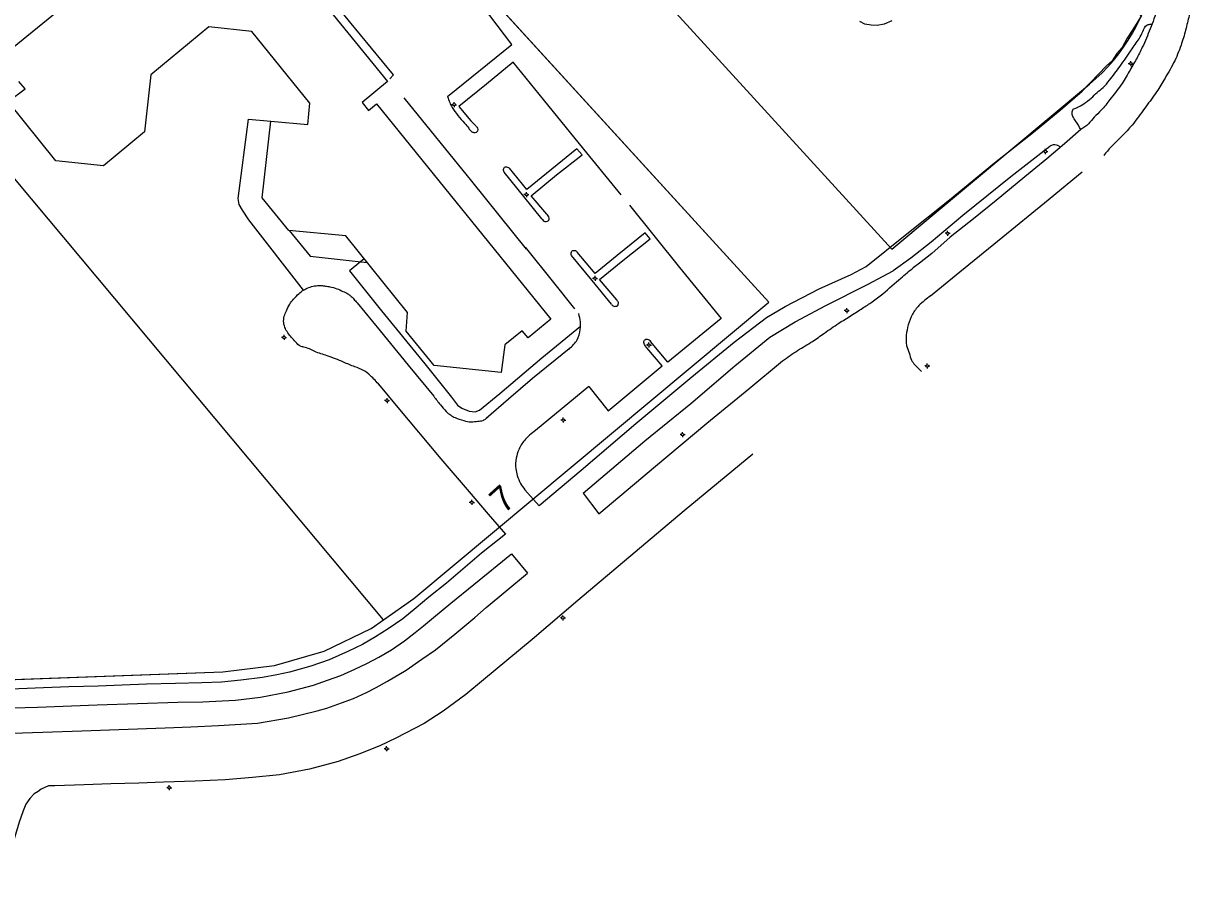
# Model space of a CAD drawing. Extents: x 1517229 to 1518128, y 6494851 to 6495271.
# Drawn here: x 1517875.8 to 1518062.3, y 6494915.9 to 6495054.4 of the extents above; entities that cross this region are included whole.
import ezdxf

# ---------------------------------------------------------------- set-up
doc = ezdxf.new("R2010")
doc.units = 0
doc.layers.add('Karta', color=7, linetype='Continuous')

msp = doc.modelspace()

# ---------------------------------------------------------------- linework, layer by layer
at = {"layer": 'Karta'}
for p, q in [((1517860.04, 6495186.49), (1518013.12, 6495018.67)), ((1517881.78, 6495132.98), (1517993.7, 6495010.28)), ((1517932.72, 6494960.01), (1517858.73, 6495048.55)), ((1518050.74, 6495048.03), (1518050.54, 6495048.03)), ((1518050.94, 6495048.23), (1518050.94, 6495048.43)), ((1518050.94, 6495047.83), (1518050.94, 6495047.63)), ((1518051.14, 6495048.03), (1518051.34, 6495048.03)), ((1518013.12, 6495018.67), (1518044.42, 6495044.79)), ((1517943.7, 6495041.55), (1517943.5, 6495041.55)), ((1517943.9, 6495041.75), (1517943.9, 6495041.95)), ((1517943.9, 6495041.35), (1517943.9, 6495041.15)), ((1517944.1, 6495041.55), (1517944.3, 6495041.55)), ((1518037.21, 6495034.14), (1518037.01, 6495034.14)), ((1518037.41, 6495034.34), (1518037.41, 6495034.54)), ((1518037.41, 6495033.94), (1518037.41, 6495033.74)), ((1518037.61, 6495034.14), (1518037.81, 6495034.14)), ((1517955.14, 6495027.31), (1517954.94, 6495027.31)), ((1517955.34, 6495027.51), (1517955.34, 6495027.71)), ((1517955.34, 6495027.11), (1517955.34, 6495026.91)), ((1517955.54, 6495027.31), (1517955.74, 6495027.31)), ((1518021.76, 6495021.2), (1518021.56, 6495021.2)), ((1518021.96, 6495021.4), (1518021.96, 6495021.6)), ((1518021.96, 6495021), (1518021.96, 6495020.8)), ((1518022.16, 6495021.2), (1518022.36, 6495021.2)), ((1517929.69, 6495017.16), (1517927.33, 6495015.24)), ((1517965.99, 6495014.06), (1517965.79, 6495014.06)), ((1517966.19, 6495014.26), (1517966.19, 6495014.46)), ((1517966.19, 6495013.86), (1517966.19, 6495013.66)), ((1517966.39, 6495014.06), (1517966.59, 6495014.06)), ((1517937.5, 6494963.37), (1517993.7, 6495010.28)), ((1517937.5, 6494963.37), (1517993.7, 6495010.28)), ((1518005.81, 6495008.96), (1518005.61, 6495008.96)), ((1518006.01, 6495009.16), (1518006.01, 6495009.36)), ((1518006.01, 6495008.76), (1518006.01, 6495008.56)), ((1518006.21, 6495008.96), (1518006.41, 6495008.96)), ((1517916.79, 6495004.71), (1517916.59, 6495004.71)), ((1517916.99, 6495004.91), (1517916.99, 6495005.11)), ((1517916.99, 6495004.51), (1517916.99, 6495004.31)), ((1517917.19, 6495004.71), (1517917.39, 6495004.71)), ((1517974.71, 6495003.71), (1517974.71, 6495003.91)), ((1517977.69, 6495000.8), (1517974.98, 6495004.06)), ((1517974.51, 6495003.51), (1517974.31, 6495003.51)), ((1517974.71, 6495003.31), (1517974.71, 6495003.11)), ((1517974.91, 6495003.51), (1517975.11, 6495003.51)), ((1518018.54, 6495000.2), (1518018.34, 6495000.2)), ((1518018.74, 6495000.4), (1518018.74, 6495000.6)), ((1518018.94, 6495000.2), (1518019.14, 6495000.2)), ((1518018.74, 6495000), (1518018.74, 6494999.8)), ((1517965.2, 6494996.93), (1517956.78, 6494990)), ((1517933.09, 6494994.71), (1517932.89, 6494994.71)), ((1517933.29, 6494994.91), (1517933.29, 6494995.11)), ((1517933.29, 6494994.51), (1517933.29, 6494994.31)), ((1517933.49, 6494994.71), (1517933.69, 6494994.71)), ((1517960.97, 6494991.63), (1517960.77, 6494991.63)), ((1517961.17, 6494991.83), (1517961.17, 6494992.03)), ((1517961.17, 6494991.43), (1517961.17, 6494991.23)), ((1517961.37, 6494991.63), (1517961.57, 6494991.63)), ((1517979.83, 6494989.34), (1517979.63, 6494989.34)), ((1517980.03, 6494989.54), (1517980.03, 6494989.74)), ((1517980.03, 6494989.14), (1517980.03, 6494988.94)), ((1517980.23, 6494989.34), (1517980.43, 6494989.34)), ((1517941.8, 6494985.5), (1517946.29, 6494980.3)), ((1517955.08, 6494980.59), (1517957.37, 6494978.04)), ((1517946.5, 6494978.61), (1517946.3, 6494978.61)), ((1517946.7, 6494978.81), (1517946.7, 6494979.01)), ((1517946.7, 6494978.41), (1517946.7, 6494978.21)), ((1517946.9, 6494978.61), (1517947.1, 6494978.61)), ((1517932.72, 6494960.01), (1517937.5, 6494963.37)), ((1517930.77, 6494958.64), (1517932.72, 6494960.01)), ((1517960.9, 6494960.33), (1517960.7, 6494960.33)), ((1517961.1, 6494960.53), (1517961.1, 6494960.73)), ((1517961.1, 6494960.13), (1517961.1, 6494959.93)), ((1517961.3, 6494960.33), (1517961.5, 6494960.33)), ((1517923.36, 6494955.07), (1517930.77, 6494958.64)), ((1517915.47, 6494952.77), (1517923.36, 6494955.07)), ((1517784.48, 6494947.28), (1517907.3, 6494951.79)), ((1517907.3, 6494951.79), (1517915.47, 6494952.77)), ((1517933.02, 6494939.61), (1517932.82, 6494939.61)), ((1517933.22, 6494939.81), (1517933.22, 6494940.01)), ((1517933.22, 6494939.41), (1517933.22, 6494939.21)), ((1517933.42, 6494939.61), (1517933.62, 6494939.61)), ((1517898.63, 6494933.44), (1517898.43, 6494933.44)), ((1517898.83, 6494933.64), (1517898.83, 6494933.84)), ((1517898.83, 6494933.24), (1517898.83, 6494933.04)), ((1517899.03, 6494933.44), (1517899.23, 6494933.44))]:
    msp.add_line(p, q, dxfattribs=at)
for points in [[(1517844.68, 6495173.66), (1517881.78, 6495132.98), (1517993.7, 6495010.28)], [(1517933.73, 6495045.66), (1517934.33, 6495046.26), (1517927.37, 6495054.74), (1517921.21, 6495062.29), (1517913.73, 6495071.44), (1517908.14, 6495078.37), (1517907.09, 6495077.52)], [(1517870.88, 6495048), (1517907.09, 6495077.52), (1517933.35, 6495045.23), (1517929.35, 6495041.89), (1517930.34, 6495040.63), (1517931.6, 6495041.66), (1517959.21, 6495007.63), (1517955.6, 6495004.66), (1517954.66, 6495005.75), (1517951.91, 6495003.55), (1517951.34, 6494999.16), (1517940.72, 6495000.25), (1517936.32, 6495005.72), (1517936.54, 6495008.66), (1517926.77, 6495020.79), (1517917.76, 6495021.62), (1517913.56, 6495026.79), (1517914.92, 6495038.96), (1517920.76, 6495038.39), (1517921.1, 6495041.77), (1517911.88, 6495053.14), (1517905.12, 6495053.86), (1517895.91, 6495046.25), (1517894.94, 6495037.25), (1517888.42, 6495031.87), (1517880.89, 6495032.64), (1517873.38, 6495042.06), (1517876.03, 6495044.05), (1517875.06, 6495045.24)], [(1517942.87, 6495042.85), (1517953.03, 6495051.06), (1517944.76, 6495062.04), (1517943.82, 6495061.29)], [(1518047.05, 6495057.36), (1518050.19, 6495056.46), (1518052.3, 6495055.83), (1518052.64, 6495055.68), (1518051.87, 6495054.47), (1518051.15, 6495053.28), (1518050.38, 6495052.07), (1518049.57, 6495050.61), (1518048.73, 6495049.65), (1518047.98, 6495048.5), (1518047.11, 6495047.69)], [(1518013.12, 6495054.84), (1518011.94, 6495054.3), (1518010.79, 6495054.09), (1518009.89, 6495054.12), (1518008.86, 6495054.3), (1518008.08, 6495054.72)], [(1517970.3, 6495027.28), (1517964.43, 6495034.5), (1517958.01, 6495042.35), (1517953.24, 6495048.28), (1517949, 6495044.8), (1517944.66, 6495041.29), (1517946.52, 6495038.97), (1517947.31, 6495038.18)], [(1518009.06, 6495015.92), (1518015.25, 6495020.88), (1518022.28, 6495026.48), (1518029.37, 6495032.34), (1518035.55, 6495037.22), (1518039.78, 6495040.67), (1518043.23, 6495043.67), (1518047.11, 6495047.69)], [(1517955.36, 6495018.69), (1517946.68, 6495029.43), (1517936.02, 6495042.61)], [(1517920.09, 6495012.22), (1517911.41, 6495023.35), (1517910.42, 6495024.84), (1517909.92, 6495025.77), (1517909.74, 6495026.69), (1517911.35, 6495039.25), (1517914.92, 6495038.96)], [(1518043.04, 6495037.61), (1518040.43, 6495035.33), (1518037.64, 6495032.99), (1518034.19, 6495030.13), (1518029.63, 6495026.41), (1518026.06, 6495023.49), (1518022.35, 6495020.56), (1518019.48, 6495018.02), (1518017.53, 6495016.45), (1518016.52, 6495015.74)], [(1517958.56, 6495024.23), (1517956.07, 6495027.14), (1517960.08, 6495030.46), (1517964.15, 6495033.64), (1517963.32, 6495034.56), (1517955.41, 6495028.14), (1517952.66, 6495031.48)], [(1518038.12, 6495034.95), (1518031.98, 6495030.13), (1518024.36, 6495024.01), (1518019.35, 6495019.77), (1518016.16, 6495017.24), (1518013.33, 6495015.28)], [(1517957.79, 6495023.5), (1517954.95, 6495027.04), (1517951.8, 6495030.85)], [(1518019.24, 6495011.3), (1518023.91, 6495015.09), (1518030.68, 6495020.62), (1518037.31, 6495026.03), (1518043.23, 6495030.91)], [(1517971.62, 6495025.65), (1517979.57, 6495015.78), (1517986.13, 6495007.7), (1517977.69, 6495000.8)], [(1517917.79, 6495021.62), (1517921.12, 6495017.59), (1517930.16, 6495016.58)], [(1517969.63, 6495010.64), (1517966.92, 6495013.89), (1517970.59, 6495016.87), (1517974.9, 6495020.32), (1517974.14, 6495021.25), (1517969.7, 6495017.7), (1517966.22, 6495014.85), (1517963.37, 6495018.23)], [(1517955.12, 6495018.99), (1517959.6, 6495013.39), (1517962.95, 6495009.26)], [(1517968.77, 6495009.98), (1517965.76, 6495013.72), (1517962.48, 6495017.7)], [(1517927.33, 6495015.24), (1517932.4, 6495008.93), (1517939.24, 6495000.53), (1517943.47, 6494995.26)], [(1517988.19, 6495003.96), (1517993.31, 6495007.88), (1517996.26, 6495009.62), (1518001.65, 6495012.4), (1518006.7, 6495014.66), (1518009.06, 6495015.92)], [(1517988.32, 6495000.24), (1517993.83, 6495004.75), (1517997.83, 6495007.18), (1518002.7, 6495009.79), (1518009.31, 6495013.1), (1518013.33, 6495015.28)], [(1517928.54, 6495010.21), (1517932.21, 6495005.74), (1517936.65, 6495000.31), (1517940.69, 6494995.4)], [(1517943.47, 6494995.26), (1517944.41, 6494994.02), (1517945.13, 6494993.5), (1517946.3, 6494993.05), (1517947.21, 6494992.92), (1517947.92, 6494993.18), (1517951.11, 6494995.85), (1517957.75, 6495001.51), (1517963.87, 6495006.52)], [(1517957.33, 6494978.09), (1517963.98, 6494983.71), (1517972.63, 6494991.07), (1517981.48, 6494998.49), (1517988.19, 6495003.96)], [(1517962.12, 6495002.89), (1517956.32, 6494998.22), (1517952.51, 6494994.94), (1517948.98, 6494991.88)], [(1517965.2, 6494996.93), (1517968.24, 6494993.12), (1517976.79, 6495000.21), (1517974.4, 6495003.06)], [(1517964.31, 6494980.07), (1517966.78, 6494976.81), (1517975.76, 6494984.36), (1517983.89, 6494991.13), (1517990.53, 6494996.6), (1517995.86, 6495001.03)], [(1517964.31, 6494980.06), (1517974.07, 6494988.33), (1517981.35, 6494994.26), (1517988.32, 6495000.24)], [(1517931.95, 6494997.31), (1517935.01, 6494993.65), (1517941.8, 6494985.5)], [(1517991.15, 6494986.25), (1517980.28, 6494977.28), (1517972.55, 6494970.74), (1517963.46, 6494963.09)], [(1517946.29, 6494980.3), (1517949.27, 6494976.75), (1517952.02, 6494973.57)], [(1517952.02, 6494973.57), (1517948.24, 6494970.56), (1517942.7, 6494965.83), (1517939.9, 6494963.59), (1517937.87, 6494961.94), (1517935.77, 6494960.16), (1517933.49, 6494958.58), (1517931.46, 6494957.32)], [(1517943.37, 6494962.65), (1517947.04, 6494965.59), (1517952.96, 6494970.49), (1517955.53, 6494967.39)], [(1517948.97, 6494961.95), (1517952.09, 6494964.54), (1517955.53, 6494967.39)], [(1517930.77, 6494958.64), (1517932.72, 6494960.01), (1517937.5, 6494963.37)], [(1517963.46, 6494963.09), (1517956.26, 6494956.9), (1517948.56, 6494950.5)], [(1517921.65, 6494949.68), (1517923.89, 6494950.45), (1517925.99, 6494951.22), (1517928.2, 6494952.2), (1517930.09, 6494953.11), (1517931.98, 6494954.1), (1517933.98, 6494955.29), (1517936.05, 6494956.69), (1517937.73, 6494958.02), (1517939.06, 6494959.07), (1517940.63, 6494960.4), (1517943.37, 6494962.65)], [(1517922.25, 6494945.62), (1517923.75, 6494946.04), (1517926.1, 6494946.88), (1517927.96, 6494947.58), (1517930.02, 6494948.52), (1517931.56, 6494949.33), (1517933.35, 6494950.31), (1517936.29, 6494952.06), (1517938.81, 6494953.78), (1517940.95, 6494955.29), (1517944, 6494957.74), (1517947.15, 6494960.4), (1517948.97, 6494961.95)], [(1517749.54, 6494952.96), (1517760.9, 6494949.53), (1517772.62, 6494947.63), (1517784.48, 6494947.28), (1517907.3, 6494951.79), (1517915.47, 6494952.77), (1517923.36, 6494955.07), (1517930.77, 6494958.64)], [(1517931.46, 6494957.32), (1517929.41, 6494956.13), (1517927.2, 6494955.04), (1517924.12, 6494953.71), (1517921.21, 6494952.69), (1517917.86, 6494951.72)], [(1517917.86, 6494951.72), (1517915.84, 6494951.29), (1517913.6, 6494950.87), (1517910.16, 6494950.45), (1517907.08, 6494950.17)], [(1517907.08, 6494950.17), (1517903.98, 6494950.06), (1517899.81, 6494949.96), (1517895.23, 6494949.82), (1517891.37, 6494949.68), (1517887.59, 6494949.5), (1517882.93, 6494949.43), (1517878.94, 6494949.26)], [(1517948.56, 6494950.5), (1517945.77, 6494948.21), (1517942.19, 6494945.58), (1517939.18, 6494943.62), (1517934.69, 6494941.28)], [(1517878.94, 6494949.26), (1517875.05, 6494949.12), (1517868.92, 6494948.91), (1517862.69, 6494948.66), (1517854.88, 6494948.42)], [(1517900.2, 6494946.98), (1517904.14, 6494947.05), (1517907.22, 6494947.19), (1517909.32, 6494947.33), (1517913.25, 6494947.79), (1517917.66, 6494948.63), (1517921.65, 6494949.68)], [(1517846.22, 6494945.16), (1517859.71, 6494945.61), (1517868.15, 6494945.93), (1517877.99, 6494946.21)], [(1517877.99, 6494946.21), (1517887.45, 6494946.56), (1517900.2, 6494946.98)], [(1517898.2, 6494942.92), (1517902.25, 6494943.06), (1517906.63, 6494943.3), (1517912.82, 6494943.69), (1517917.69, 6494944.49), (1517922.25, 6494945.62)], [(1517846.64, 6494941.09), (1517859.29, 6494941.55), (1517867.48, 6494941.86), (1517878.83, 6494942.25)], [(1517878.83, 6494942.25), (1517885.03, 6494942.46), (1517898.2, 6494942.92)], [(1517934.69, 6494941.28), (1517932.16, 6494940.08), (1517928.83, 6494938.78), (1517925.58, 6494937.59), (1517921.02, 6494936.4), (1517916.26, 6494935.49), (1517912.02, 6494935.07), (1517907.68, 6494934.68)], [(1517878.59, 6494933.21), (1517878.1, 6494932.86), (1517877.47, 6494932.47), (1517876.8, 6494931.74), (1517876.17, 6494930.86), (1517875.75, 6494929.81), (1517875.12, 6494928.02), (1517874.35, 6494925.54), (1517873.79, 6494923.92), (1517873.3, 6494923.01), (1517872.67, 6494922.07), (1517872.21, 6494921.33), (1517871.27, 6494920.24), (1517870.43, 6494919.51), (1517869.55, 6494918.84), (1517868.33, 6494918.07), (1517866.89, 6494917.41), (1517865.18, 6494916.57), (1517863.73, 6494915.92)], [(1517907.68, 6494934.68), (1517902.93, 6494934.47), (1517897.92, 6494934.33), (1517894, 6494934.19), (1517889.59, 6494934.05), (1517885.38, 6494933.91), (1517880.76, 6494933.74), (1517879.73, 6494933.73), (1517878.59, 6494933.21)]]:
    msp.add_lwpolyline(points, dxfattribs=at)
for centre in [(1518050.94, 6495048.03), (1517943.9, 6495041.55), (1518037.41, 6495034.14), (1517955.34, 6495027.31), (1518021.96, 6495021.2), (1517966.19, 6495014.06), (1518006.01, 6495008.96), (1517916.99, 6495004.71), (1517974.71, 6495003.51), (1518018.74, 6495000.2), (1517933.29, 6494994.71), (1517961.17, 6494991.63), (1517980.03, 6494989.34), (1517946.7, 6494978.61), (1517961.1, 6494960.33), (1517933.22, 6494939.61), (1517898.83, 6494933.44)]:
    msp.add_circle(centre, 0.2, dxfattribs=at)
msp.add_arc((1518025.19, 6495067.83), 30.01, 309.8505, 350.4132, dxfattribs=at)
for points in [[(1518056.47, 6495063.98), (1518055.89, 6495060.46), (1518055.11, 6495056.69), (1518054, 6495053.56), (1518052.76, 6495050.63), (1518051.79, 6495048.75), (1518050.68, 6495046.79), (1518049.38, 6495044.64), (1518047.63, 6495042.37), (1518046.26, 6495040.67), (1518045.15, 6495039.57), (1518044.24, 6495038.52), (1518043.02, 6495037.6)], [(1518062.27, 6495065.15), (1518061.68, 6495062.09), (1518061.03, 6495058.31), (1518060.18, 6495055.65), (1518059.6, 6495053.37), (1518058.88, 6495050.96), (1518057.71, 6495048.16), (1518056.15, 6495045.42), (1518054.85, 6495043.34), (1518053.09, 6495040.93), (1518051.14, 6495038.33), (1518049.51, 6495036.57), (1518047.82, 6495034.88), (1518046.65, 6495033.51)], [(1518043.04, 6495037.61), (1518042.21, 6495038.99), (1518041.77, 6495039.7), (1518041.66, 6495040.3), (1518041.82, 6495040.82), (1518042.37, 6495041.07), (1518043.49, 6495041.7), (1518044.67, 6495042.6), (1518045.6, 6495043.48), (1518046.55, 6495044.27), (1518047.56, 6495045.42), (1518049.25, 6495047.64), (1518051.01, 6495050.18), (1518052.24, 6495052), (1518052.83, 6495053.11), (1518053.48, 6495054.15), (1518053.94, 6495054.28), (1518054.29, 6495054.29)], [(1517942.87, 6495042.85), (1517943.2, 6495041.89), (1517943.57, 6495041.12), (1517944.5, 6495039.86), (1517945.56, 6495038.61), (1517946.22, 6495037.81), (1517946.58, 6495037.35), (1517947.01, 6495037.15), (1517947.44, 6495037.21), (1517947.64, 6495037.41), (1517947.64, 6495037.81), (1517947.31, 6495038.18)], [(1518039.82, 6495034.82), (1518039.4, 6495035.09), (1518038.94, 6495035.2), (1518038.37, 6495035.09), (1518038.12, 6495034.95)], [(1517951.8, 6495030.85), (1517951.7, 6495031.16), (1517951.76, 6495031.47), (1517951.88, 6495031.65), (1517952.18, 6495031.7), (1517952.48, 6495031.63), (1517952.66, 6495031.48)], [(1517957.79, 6495023.5), (1517958.27, 6495023.07), (1517958.68, 6495023.1), (1517958.88, 6495023.29), (1517958.92, 6495023.61), (1517958.79, 6495023.98), (1517958.56, 6495024.23)], [(1517962.48, 6495017.7), (1517962.41, 6495017.95), (1517962.47, 6495018.26), (1517962.56, 6495018.42), (1517962.83, 6495018.46), (1517963.09, 6495018.46), (1517963.24, 6495018.35), (1517963.37, 6495018.23)], [(1517995.86, 6495001.02), (1517998.24, 6495002.65), (1518000.58, 6495004.09), (1518002.47, 6495005.39), (1518004.74, 6495006.95), (1518006.7, 6495008.19), (1518008.52, 6495009.36), (1518010.02, 6495010.34), (1518011.71, 6495011.64), (1518014.57, 6495014.11), (1518016.52, 6495015.74)], [(1517917.21, 6495006.1), (1517916.94, 6495007.03), (1517917.04, 6495008.06), (1517917.37, 6495008.92), (1517917.9, 6495009.98), (1517918.5, 6495010.77), (1517919.33, 6495011.64), (1517920.06, 6495012.2), (1517920.89, 6495012.6), (1517921.81, 6495012.86), (1517922.81, 6495012.93), (1517923.57, 6495012.83), (1517924.23, 6495012.73), (1517925.36, 6495012.43), (1517926.32, 6495012), (1517927.11, 6495011.6), (1517927.48, 6495011.34), (1517928.04, 6495010.77), (1517928.54, 6495010.21)], [(1518019.26, 6495011.31), (1518017.43, 6495009.75), (1518016.39, 6495008.38), (1518015.74, 6495006.69), (1518015.42, 6495005.06), (1518015.48, 6495003.44), (1518015.87, 6495002.26), (1518016.26, 6495001.09), (1518016.78, 6495000.38), (1518017.82, 6494999.33)], [(1517968.77, 6495009.98), (1517969.15, 6495009.66), (1517969.49, 6495009.64), (1517969.75, 6495009.74), (1517969.87, 6495010.01), (1517969.89, 6495010.26), (1517969.76, 6495010.48), (1517969.63, 6495010.64)], [(1517962.09, 6495002.87), (1517963.36, 6495004.35), (1517963.85, 6495005.97), (1517963.88, 6495007.18), (1517963.62, 6495008.48)], [(1517932.1, 6494997.16), (1517930.64, 6494998.68), (1517929.58, 6494999.48), (1517928.19, 6495000.07), (1517926.4, 6495000.8), (1517923.82, 6495001.8), (1517921.85, 6495002.49), (1517920.12, 6495003.19), (1517919.58, 6495003.32), (1517918.83, 6495004.01), (1517917.59, 6495005.44), (1517917.13, 6495006.23)], [(1517974.4, 6495003.06), (1517974.02, 6495003.59), (1517973.91, 6495003.92), (1517973.94, 6495004.19), (1517974.05, 6495004.33), (1517974.41, 6495004.44), (1517974.73, 6495004.33), (1517974.98, 6495004.06)], [(1517940.69, 6494995.4), (1517941.73, 6494994.04), (1517942.66, 6494992.98), (1517944.05, 6494992.02), (1517945.41, 6494991.56), (1517946.57, 6494991.36), (1517947.63, 6494991.46), (1517948.49, 6494991.59), (1517948.99, 6494991.89), (1517949.32, 6494992.22)], [(1517956.78, 6494990), (1517955.01, 6494988.41), (1517954.12, 6494986.92), (1517953.72, 6494985.63), (1517953.65, 6494983.94), (1517953.89, 6494982.85), (1517954.42, 6494981.62), (1517955.08, 6494980.59)]]:
    msp.add_spline(points, degree=3, dxfattribs=at)

# ---------------------------------------------------------------- texts
msp.add_text('7', height=4, rotation=42.0101, dxfattribs=at).set_placement((1517951.75, 6494976.69))

doc.saveas('drawing.dxf')
